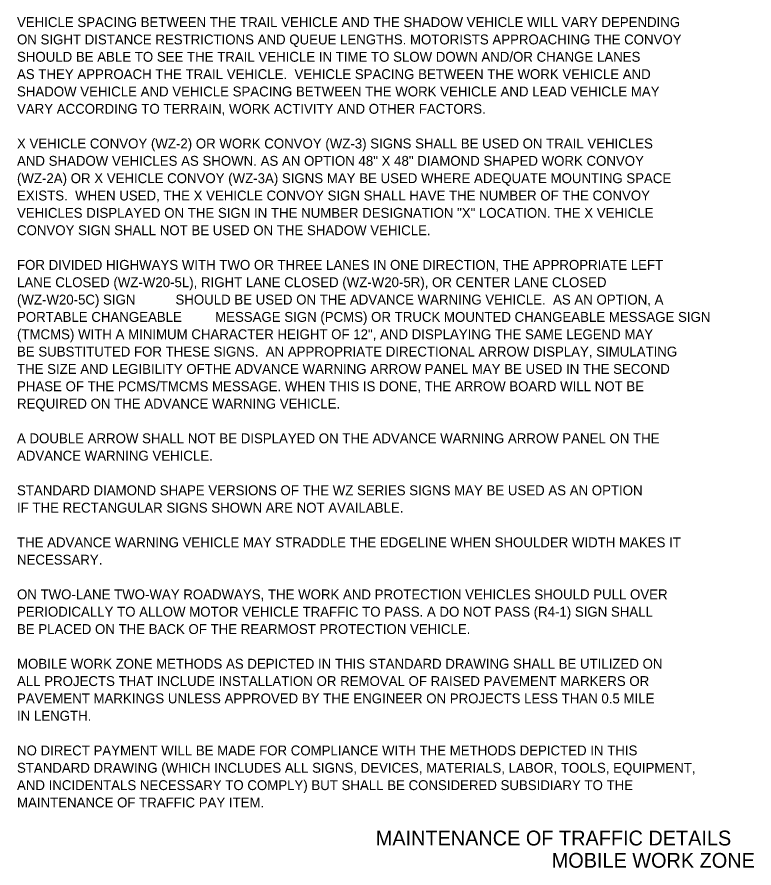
# Model space of a CAD drawing. Extents: x 1373848 to 1374003, y 380642 to 381248.
# Drawn here: x 1373958.8 to 1374003.4, y 380978.4 to 381029.9 of the extents above; entities that cross this region are included whole.
import ezdxf

# ---------------------------------------------------------------- set-up
doc = ezdxf.new("R2010")
doc.units = 0
doc.layers.add('G-ANNO-TEXT', color=7, linetype='Continuous')
doc.layers.add('Working Level 1', color=7, linetype='Continuous')

msp = doc.modelspace()

# ---------------------------------------------------------------- texts
at = {"layer": 'G-ANNO-TEXT'}
for s, p in [('MAINTENANCE OF TRAFFIC DETAILS', (1373980.522, 380979.745)), ('MOBILE WORK ZONE', (1373991.18, 380978.395))]:
    msp.add_text(s, height=0.9, dxfattribs=at).set_placement(p)
at = {"layer": 'Working Level 1'}
for s, p in [('VEHICLE SPACING BETWEEN THE TRAIL VEHICLE AND THE SHADOW VEHICLE WILL VARY DEPENDING ', (1373958.79, 381029.298)), ('ON SIGHT DISTANCE RESTRICTIONS AND QUEUE LENGTHS. MOTORISTS APPROACHING THE CONVOY ', (1373958.79, 381028.248)), ('SHOULD BE ABLE TO SEE THE TRAIL VEHICLE IN TIME TO SLOW DOWN AND/OR CHANGE LANES ', (1373958.79, 381027.198)), ('AS THEY APPROACH THE TRAIL VEHICLE.  VEHICLE SPACING BETWEEN THE WORK VEHICLE AND ', (1373958.79, 381026.148)), ('SHADOW VEHICLE AND VEHICLE SPACING BETWEEN THE WORK VEHICLE AND LEAD VEHICLE MAY ', (1373958.79, 381025.098)), ('VARY ACCORDING TO TERRAIN, WORK ACTIVITY AND OTHER FACTORS.', (1373958.79, 381024.048)), ('X VEHICLE CONVOY (WZ-2) OR WORK CONVOY (WZ-3) SIGNS SHALL BE USED ON TRAIL VEHICLES', (1373958.79, 381021.948)), ('AND SHADOW VEHICLES AS SHOWN. AS AN OPTION 48" X 48" DIAMOND SHAPED WORK CONVOY', (1373958.79, 381020.898)), ('(WZ-2A) OR X VEHICLE CONVOY (WZ-3A) SIGNS MAY BE USED WHERE ADEQUATE MOUNTING SPACE', (1373958.79, 381019.848)), ('EXISTS.  WHEN USED, THE X VEHICLE CONVOY SIGN SHALL HAVE THE NUMBER OF THE CONVOY', (1373958.79, 381018.798)), ('VEHICLES DISPLAYED ON THE SIGN IN THE NUMBER DESIGNATION "X" LOCATION. THE X VEHICLE', (1373958.79, 381017.748)), ('CONVOY SIGN SHALL NOT BE USED ON THE SHADOW VEHICLE.', (1373958.79, 381016.698)), ('FOR DIVIDED HIGHWAYS WITH TWO OR THREE LANES IN ONE DIRECTION, THE APPROPRIATE LEFT ', (1373958.79, 381014.598)), ('LANE CLOSED (WZ-W20-5L), RIGHT LANE CLOSED (WZ-W20-5R), OR CENTER LANE CLOSED ', (1373958.79, 381013.548)), ('(WZ-W20-5C) SIGN', (1373958.79, 381012.498)), ('SHOULD BE USED ON THE ADVANCE WARNING VEHICLE.  AS AN OPTION, A ', (1373968.39, 381012.498)), ('PORTABLE CHANGEABLE', (1373958.79, 381011.448)), ('MESSAGE SIGN (PCMS) OR TRUCK MOUNTED CHANGEABLE MESSAGE SIGN ', (1373970.79, 381011.448)), ('(TMCMS) WITH A MINIMUM CHARACTER HEIGHT OF 12", AND DISPLAYING THE SAME LEGEND MAY ', (1373958.79, 381010.398)), ('BE SUBSTITUTED FOR THESE SIGNS.  AN APPROPRIATE DIRECTIONAL ARROW DISPLAY, SIMULATING ', (1373958.79, 381009.348)), ('THE SIZE AND LEGIBILITY OFTHE ADVANCE WARNING ARROW PANEL MAY BE USED IN THE SECOND ', (1373958.79, 381008.298)), ('PHASE OF THE PCMS/TMCMS MESSAGE. WHEN THIS IS DONE, THE ARROW BOARD WILL NOT BE ', (1373958.79, 381007.248)), ('REQUIRED ON THE ADVANCE WARNING VEHICLE.', (1373958.79, 381006.198)), ('A DOUBLE ARROW SHALL NOT BE DISPLAYED ON THE ADVANCE WARNING ARROW PANEL ON THE ', (1373958.79, 381004.098)), ('ADVANCE WARNING VEHICLE. ', (1373958.79, 381003.048)), ('STANDARD DIAMOND SHAPE VERSIONS OF THE WZ SERIES SIGNS MAY BE USED AS AN OPTION ', (1373958.79, 381000.948)), ('IF THE RECTANGULAR SIGNS SHOWN ARE NOT AVAILABLE.', (1373958.79, 380999.898)), ('THE ADVANCE WARNING VEHICLE MAY STRADDLE THE EDGELINE WHEN SHOULDER WIDTH MAKES IT ', (1373958.79, 380997.798)), ('NECESSARY.', (1373958.79, 380996.748)), ('ON TWO-LANE TWO-WAY ROADWAYS, THE WORK AND PROTECTION VEHICLES SHOULD PULL OVER', (1373958.79, 380994.648)), ('PERIODICALLY TO ALLOW MOTOR VEHICLE TRAFFIC TO PASS. A DO NOT PASS (R4-1) SIGN SHALL ', (1373958.79, 380993.598)), ('BE PLACED ON THE BACK OF THE REARMOST PROTECTION VEHICLE.', (1373958.79, 380992.548)), ('MOBILE WORK ZONE METHODS AS DEPICTED IN THIS STANDARD DRAWING SHALL BE UTILIZED ON ', (1373958.79, 380990.448)), ('ALL PROJECTS THAT INCLUDE INSTALLATION OR REMOVAL OF RAISED PAVEMENT MARKERS OR ', (1373958.79, 380989.398)), ('PAVEMENT MARKINGS UNLESS APPROVED BY THE ENGINEER ON PROJECTS LESS THAN 0.5 MILE ', (1373958.79, 380988.348)), ('IN LENGTH.', (1373958.79, 380987.298)), ('NO DIRECT PAYMENT WILL BE MADE FOR COMPLIANCE WITH THE METHODS DEPICTED IN THIS ', (1373958.79, 380985.198)), ('STANDARD DRAWING (WHICH INCLUDES ALL SIGNS, DEVICES, MATERIALS, LABOR, TOOLS, EQUIPMENT, ', (1373958.79, 380984.148)), ('AND INCIDENTALS NECESSARY TO COMPLY) BUT SHALL BE CONSIDERED SUBSIDIARY TO THE ', (1373958.79, 380983.098)), ('MAINTENANCE OF TRAFFIC PAY ITEM.', (1373958.79, 380982.048))]:
    msp.add_text(s, height=0.6, dxfattribs=at).set_placement(p)

doc.saveas('drawing.dxf')
